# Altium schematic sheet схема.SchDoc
size A4
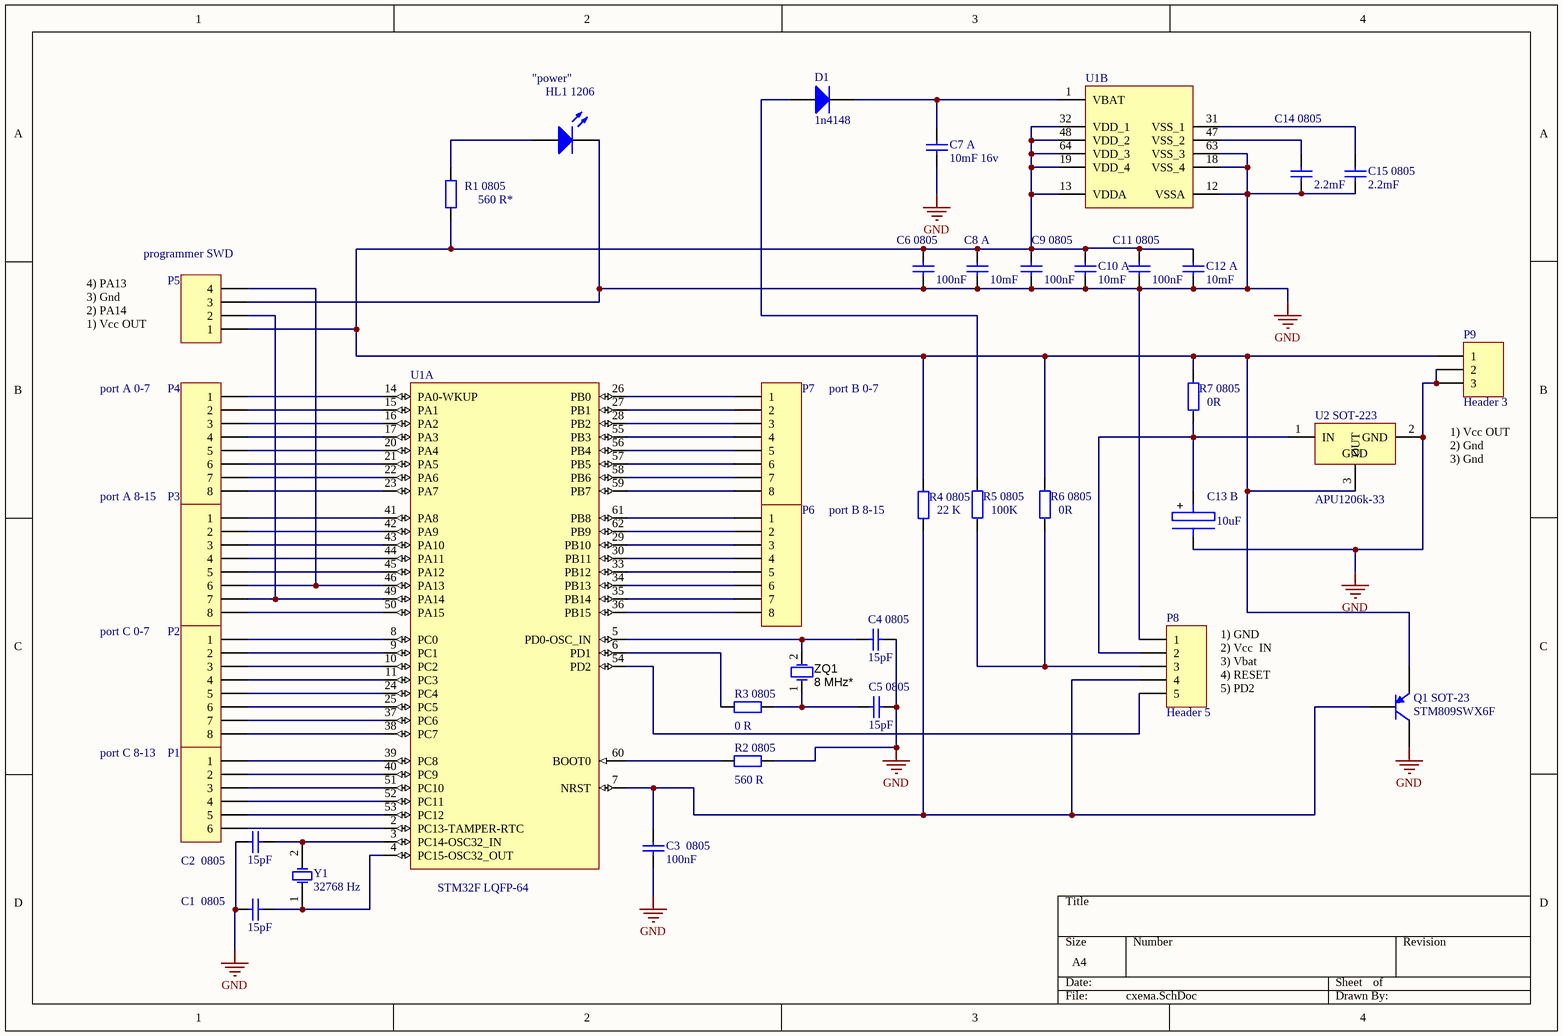
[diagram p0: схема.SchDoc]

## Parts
C1_0805  value 15pF  [C0805]  (hidden comment: Cap Semi)
C2_0805  value 15pF  [C0805]  (hidden comment: Cap Semi)
C3_0805  value 100nF  [C1206]  (hidden comment: Cap Semi)
C4_0805  value 15pF  [C0805]  (hidden comment: Cap Semi)
C5_0805  value 15pF  [C0805]  (hidden comment: Cap Semi)
C6_0805  value 100nF  [C0805]  (hidden comment: Cap Semi)
C7_A  value 10mF 16v  [6032 - Type C]  (hidden comment: Cap Semi)
C8_A  value 10mF  [C1206]  (hidden comment: Cap Semi)
C9_0805  value 100nF  [C0805]  (hidden comment: Cap Semi)
C10_A  value 10mF  [C0805 - wa]  (hidden comment: Cap Semi)
C11_0805  value 100nF  [C0805]  (hidden comment: Cap Semi)
C12_A  value 10mF  [C0805 - wa]  (hidden comment: Cap Semi)
C13_B  value 10uF  [3528 - Type B]  (hidden comment: Cap polar_Vishay Type B)
C14_0805  value 2.2mF  [C0805]  (hidden comment: Cap Semi)
C15_0805  value 2.2mF  [C0805]  (hidden comment: Cap Semi)
D1  1n4148  [MELF]
HL1_1206  "power"  [C1206]
P1  port C 8-13  [HDR1X6]
P2  port C 0-7  [HDR1X8]
P3  port A 8-15  [HDR1X8]
P4  port A 0-7  [HDR1X8]
P5  programmer SWD  [HDR1X4]
P6  port B 8-15  [HDR1X8]
P7  port B 0-7  [HDR1X8]
P8  Header 5  [HDR1X5]
P9  Header 3  [HDR1X3]
Q1_SOT-23  STM809SWX6F  [SOT-23B_N]
R1_0805  value 560 R*  [C0805]  (hidden comment: Res2)
R2_0805  value 560 R  [C0805]  (hidden comment: Res2)
R3_0805  value 0 R  [C0805]  (hidden comment: Res2)
R4_0805  value 22 K  [C0805]  (hidden comment: Resistor 1206)
R5_0805  value 100K  [C0805]  (hidden comment: Res2)
R6_0805  value 0R  [C0805]  (hidden comment: Res2)
R7_0805  value 0R  [C0805]  (hidden comment: Res2)
U1  STM32F LQFP-64  [LQFP64_N]  (parts A,B of 2)
U2_SOT-223  APU1206k-33  [DPAK]
Y1  32768 Hz  [R38]
ZQ1  8 MHz*  [HC49S]

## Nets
GND: C1_0805.2 C2_0805.2 C3_0805.2 C4_0805.2 C5_0805.2 C6_0805.1 C7_A.2 C8_A.1 C9_0805.2 C10_A.2 C11_0805.1 C12_A.1 C13_B.2 C14_0805.1 C15_0805.1 HL1_1206.2(K) P5.3 P8.1 P9.2 P9.3 Q1_SOT-23.1(C) R2_0805.2 U1.12(VSSA) U1.18(VSS_4) U1.63(VSS_3) U2_SOT-223.2(GND)
NetC1_0805_1: C1_0805.1 U1.4(PC15-OSC32_OUT) Y1.1(OSC1)
NetC2_0805_1: C2_0805.1 U1.3(PC14-OSC32_IN) Y1.2(OSC2)
NetC3_0805_1: C3_0805.1 P8.4 Q1_SOT-23.2(B) R4_0805.1 U1.7(NRST)
NetC4_0805_1: C4_0805.1 U1.5(PD0-OSC_IN) ZQ1.2(OSC2)
NetC5_0805_1: C5_0805.1 R3_0805.2 ZQ1.1(OSC1)
NetC6_0805_2: C6_0805.2 C8_A.2 C9_0805.1 C10_A.1 C11_0805.2 C12_A.2 P5.1 P9.1 Q1_SOT-23.3(E) R1_0805.1 R4_0805.2 R6_0805.2 R7_0805.2 U1.13(VDDA) U1.19(VDD_4) U1.32(VDD_1) U1.48(VDD_2) U1.64(VDD_3) U2_SOT-223.3(OUT)
NetC7_A_1: C7_A.1 D1.2(K) U1.1(VBAT)
NetC13_B_1: C13_B.1 P8.2 R7_0805.1 U2_SOT-223.1(IN)
NetC14_0805_2: C14_0805.2 U1.47(VSS_2)
NetC15_0805_2: C15_0805.2 U1.31(VSS_1)
NetD1_1: D1.1(A) R5_0805.2
NetHL1_1206_1: HL1_1206.1(A) R1_0805.2
NetP1_1: P1.1 U1.39(PC8)
NetP1_2: P1.2 U1.40(PC9)
NetP1_3: P1.3 U1.51(PC10)
NetP1_4: P1.4 U1.52(PC11)
NetP1_5: P1.5 U1.53(PC12)
NetP1_6: P1.6 U1.2(PC13-TAMPER-RTC)
NetP2_1: P2.1 U1.8(PC0)
NetP2_2: P2.2 U1.9(PC1)
NetP2_3: P2.3 U1.10(PC2)
NetP2_4: P2.4 U1.11(PC3)
NetP2_5: P2.5 U1.24(PC4)
NetP2_6: P2.6 U1.25(PC5)
NetP2_7: P2.7 U1.37(PC6)
NetP2_8: P2.8 U1.38(PC7)
NetP3_1: P3.1 U1.41(PA8)
NetP3_2: P3.2 U1.42(PA9)
NetP3_3: P3.3 U1.43(PA10)
NetP3_4: P3.4 U1.44(PA11)
NetP3_5: P3.5 U1.45(PA12)
NetP3_6: P3.6 P5.4 U1.46(PA13)
NetP3_7: P3.7 P5.2 U1.49(PA14)
NetP3_8: P3.8 U1.50(PA15)
NetP4_1: P4.1 U1.14(PA0-WKUP)
NetP4_2: P4.2 U1.15(PA1)
NetP4_3: P4.3 U1.16(PA2)
NetP4_4: P4.4 U1.17(PA3)
NetP4_5: P4.5 U1.20(PA4)
NetP4_6: P4.6 U1.21(PA5)
NetP4_7: P4.7 U1.22(PA6)
NetP4_8: P4.8 U1.23(PA7)
NetP6_1: P6.1 U1.61(PB8)
NetP6_2: P6.2 U1.62(PB9)
NetP6_3: P6.3 U1.29(PB10)
NetP6_4: P6.4 U1.30(PB11)
NetP6_5: P6.5 U1.33(PB12)
NetP6_6: P6.6 U1.34(PB13)
NetP6_7: P6.7 U1.35(PB14)
NetP6_8: P6.8 U1.36(PB15)
NetP7_1: P7.1 U1.26(PB0)
NetP7_2: P7.2 U1.27(PB1)
NetP7_3: P7.3 U1.28(PB2)
NetP7_4: P7.4 U1.55(PB3)
NetP7_5: P7.5 U1.56(PB4)
NetP7_6: P7.6 U1.57(PB5)
NetP7_7: P7.7 U1.58(PB6)
NetP7_8: P7.8 U1.59(PB7)
NetP8_3: P8.3 R5_0805.1 R6_0805.1
NetP8_5: P8.5 U1.54(PD2)
NetR2_0805_1: R2_0805.1 U1.60(BOOT0)
NetR3_0805_1: R3_0805.1 U1.6(PD1)

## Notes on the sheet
- 4) PA13
  3) Gnd
  2) PA14
  1) Vcc OUT
- 1) Vcc OUT
  2) Gnd
  3) Gnd
- 1) GND
  2) Vcc  IN
  3) Vbat
  4) RESET
  5) PD2

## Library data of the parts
C1_0805 C2_0805 C3_0805 C4_0805 C5_0805 C6_0805 C7_A C8_A C9_0805 C10_A C11_0805 C12_A C14_0805 C15_0805 = Cap Semi: Capacitor (Semiconductor SIM Model)
C13_B = Cap polar_Vishay Type B: Capacitor (Model Sergeev)
D1 = SM4001: Диод SMD 1A, 1000V; Разработал: Сергеев
HL1_1206 = LED CMD: Typical INFRARED GaAs LED
P1 = Header 6: Header, 6-Pin
P2-P4 P6 P7 = Header 8: Header, 8-Pin
P5 = Header 4: Header, 4-Pin
P8 = Header 5: Header, 5-Pin
P9 = Header 3: Header, 3-Pin
Q1_SOT-23 = PNP: PNP Bipolar Transistor
R1_0805 R2_0805 R3_0805 R5_0805 R6_0805 R7_0805 = Res2: Resistor
U1 = STM32F107RCT6TR: STM32 ARM-based 32-bit MCU Connectivity Line & Ethernet with 256 kB Flash, 64 kB Internal RAM, -40 to +85°C Temperature, 64-Pin LQFP, Tape and Reel
U2_SOT-223 = L7805ABV: Precision 1A Regulator; Note: Tab is connected to pin 3 (GND).
Y1 ZQ1 = XTAL: Crystal Oscillator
